(* Logix 5000 project; controller DF1_MSG_Sample 1756-L63 rev 19.11; software revision 19.01 *)

TASK MainTask (continuous, watchdog 500 ms) : MainProgram

MODULES
   Local : 1756-L63 (ICP 0, rev 19.11)
      Ethernet : vendor 1 type 12 code 200 (ICP 1, Ethernet 192.168.1.101, rev 3.1)
         DF1Messenger : ETHERNET-MODULE (Ethernet 192.168.1.41, rev 1.1, Output RPI 500 ms)
END_MODULES

TYPE PLX51DF1MSGDataType :
STRUCT
   BOOLEAN : BOOL;
   INT : BOOL;
   REAL : BOOL;
END_STRUCT
END_TYPE

TYPE PLX51DF1MSGFunctionType :
STRUCT
   PLC5TypedRead : BOOL;
   PLC5TypedWrite : BOOL;
   SLCTypedRead : BOOL;
   SLCTypedWrite : BOOL;
END_STRUCT
END_TYPE

TYPE PLX51DF1MSGInput :
STRUCT
   Instance : STRING;
   Status : PLX51DF1MSGStatus;
   TransactionRate : DINT;
   Temperature : REAL;
   DF1RxPacketCount : DINT;
   DF1TxPacketCount : DINT;
   DF1ChecksumErrors : DINT;
   PCCCRequests : DINT;
   PCCCFailures : DINT;
   TagReads : DINT;
   TagWrites : DINT;
   TagConnectionFailures : DINT;
   TagErrors : DINT;
END_STRUCT
END_TYPE

TYPE PLX51DF1MSGOutput :
STRUCT
   RoutingInhibit : BOOL;
END_STRUCT
END_TYPE

TYPE PLX51DF1MSGStatus :
STRUCT
   Reserved0 : BOOL;
   DF1SlaveMode : BOOL;
   ScheduledMode : BOOL;
   Reserved1 : BOOL;
   ConfigurationValid : BOOL;
   RoutingInhibited : BOOL;
   Reserved3 : BOOL;
   Reserved4 : BOOL;
   ScheduledTagStatus0 : BOOL;
   ScheduledTagStatus1 : BOOL;
   ScheduledTagStatus2 : BOOL;
   ScheduledTagStatus3 : BOOL;
   ScheduledTagStatus4 : BOOL;
   ScheduledTagStatus5 : BOOL;
   ScheduledTagStatus6 : BOOL;
   ScheduledTagStatus7 : BOOL;
   ScheduledTagStatus8 : BOOL;
   ScheduledTagStatus9 : BOOL;
   ScheduledTagStatus10 : BOOL;
   ScheduledTagStatus11 : BOOL;
   ScheduledTagStatus12 : BOOL;
   ScheduledTagStatus13 : BOOL;
   ScheduledTagStatus14 : BOOL;
   ScheduledTagStatus15 : BOOL;
   ScheduledTagStatus16 : BOOL;
   ScheduledTagStatus17 : BOOL;
   ScheduledTagStatus18 : BOOL;
   ScheduledTagStatus19 : BOOL;
END_STRUCT
END_TYPE

TYPE PLX51MessengerMsgRequest :
STRUCT
   DestinationNode : INT;
   DF1DataFileAddress : STRING;
   Function : PLX51DF1MSGFunctionType;
   DataType : PLX51DF1MSGDataType;
   ElementCount : INT;
   RequestData : INT[128];
END_STRUCT
END_TYPE

TYPE PLX51MessengerMsgResponse :
STRUCT
   Status : INT;
   ResponseLength : INT;
   ResponseData : INT[128];
END_STRUCT
END_TYPE

VAR_GLOBAL   (* controller tags *)
   DF1MSGInput : PLX51DF1MSGInput := (Instance := 'DF1 Messenger', Status.DF1SlaveMode := 1, Status.ConfigurationValid := 1);
   DF1MSGMessage : MESSAGE;
        MessageParameters(ServiceCode := 16#006a, LocalElement := DF1MSGMsgRequest, DestinationTag := DF1MSGMsgResponse, ...)
   DF1MSGMsgRequest : PLX51MessengerMsgRequest := (DestinationNode := 5, DF1DataFileAddress := 'N10:0', Function.PLC5TypedRead := 1, DataType.INT := 1, ElementCount := 16);
   DF1MSGMsgResponse : PLX51MessengerMsgResponse;
   DF1MSGOutput : PLX51DF1MSGOutput;
   DF1MsgTrigger : BOOL;
END_VAR

PROGRAM MainProgram   (* main routine MainRoutine *)

ROUTINE MainRoutine   (* ladder *)
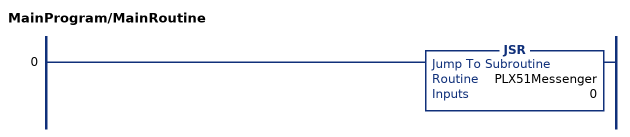
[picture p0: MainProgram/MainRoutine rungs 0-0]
   0: JSR(PLX51Messenger,0);
END_ROUTINE

ROUTINE PLX51Messenger   (* ladder *)
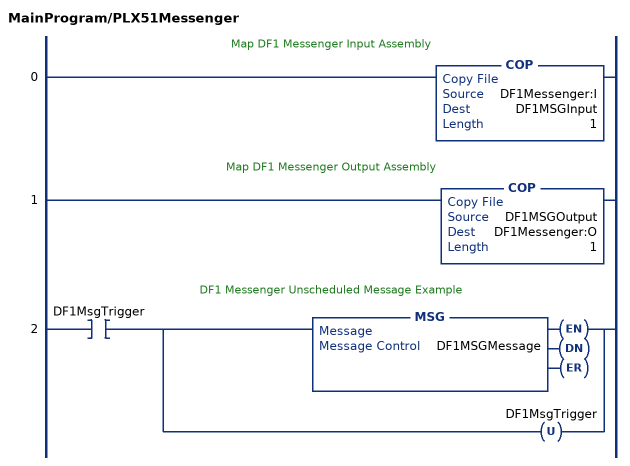
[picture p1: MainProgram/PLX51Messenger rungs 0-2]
   // Map DF1 Messenger Input Assembly
   0: COP(DF1Messenger:I,DF1MSGInput,1);
   // Map DF1 Messenger Output Assembly
   1: COP(DF1MSGOutput,DF1Messenger:O,1);
   // DF1 Messenger Unscheduled Message Example
   2: XIC(DF1MsgTrigger)[MSG(DF1MSGMessage) ,OTU(DF1MsgTrigger) ];
END_ROUTINE
END_PROGRAM
